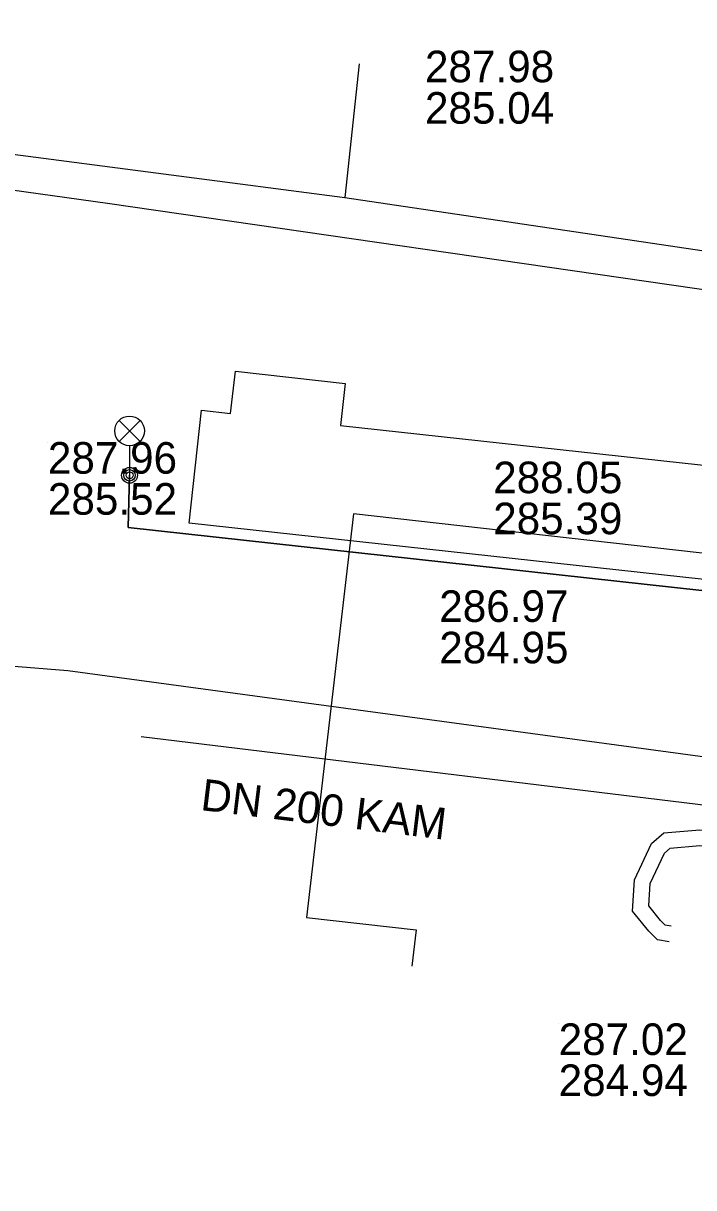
# Model space of a CAD drawing. Extents: x -595540 to -593988, y -1160850 to -1159202.
# Drawn here: x -594122.91 to -594105.92, y -1160212.47 to -1160182.95 of the extents above; entities that cross this region are included whole.
import ezdxf

# ---------------------------------------------------------------- set-up
doc = ezdxf.new("R2010")
doc.units = 0
for name, color, linetype in [('BVK-SPLASKOVA_popisy', 7, 'Continuous'), ('BVK-SPLASKOVA_trasa sítě', 7, 'Continuous'), ('DESTOVA-NEPROVOZOVANA_popisy', 7, 'Continuous'), ('DESTOVA_trasa neprovozované sítě', 7, 'Continuous'), ('EON-NN_kabel', 7, 'Continuous'), ('SPLASKOVA_neprovozovaná  trasa sítě', 7, 'Continuous'), ('SPLASKOVA_popisy neprovozované sítě', 7, 'Continuous'), ('TEPLARNY-TEPLOVODY_trasa sítě', 7, 'Continuous'), ('TSB_kabel VO', 7, 'Continuous'), ('TSB_kolektor', 7, 'Continuous'), ('TSB_lampy VO', 7, 'Continuous')]:
    doc.layers.add(name, color=color, linetype=linetype)

msp = doc.modelspace()

# ---------------------------------------------------------------- linework, layer by layer
at = {"layer": 'BVK-SPLASKOVA_popisy'}
for p, q in [((-594122.285, -1160193.567), (-594122.285, -1160193.567)), ((-594111.003, -1160194.062), (-594111.003, -1160194.062))]:
    msp.add_line(p, q, dxfattribs=at)
at = {"layer": 'BVK-SPLASKOVA_trasa sítě'}
for p, q in [((-594125.397, -1160186.863), (-594120.777, -1160187.51)), ((-594120.777, -1160187.51), (-594104.246, -1160189.903))]:
    msp.add_line(p, q, dxfattribs=at)
at = {"layer": 'DESTOVA-NEPROVOZOVANA_popisy'}
for p, q in [((-594112.731, -1160185.496), (-594112.731, -1160185.496)), ((-594112.369, -1160199.175), (-594112.369, -1160199.175))]:
    msp.add_line(p, q, dxfattribs=at)
at = {"layer": 'DESTOVA_trasa neprovozované sítě'}
for p, q in [((-594114.4, -1160183.982), (-594114.765, -1160187.369)), ((-594126.416, -1160185.847), (-594114.765, -1160187.369)), ((-594114.765, -1160187.369), (-594105.204, -1160188.788)), ((-594137.489, -1160198.059), (-594121.779, -1160199.36)), ((-594121.779, -1160199.36), (-594104.789, -1160201.659))]:
    msp.add_line(p, q, dxfattribs=at)
at = {"layer": 'EON-NN_kabel'}
for points in [[(-594106.543, -1160206.234), (-594106.84, -1160206.182), (-594107.062, -1160205.96), (-594107.47, -1160205.453), (-594107.421, -1160204.659), (-594106.991, -1160203.738), (-594106.684, -1160203.469), (-594105.765, -1160203.392), (-594104.788, -1160203.502), (-594101.807, -1160202.427), (-594101.138, -1160202.092), (-594099.842, -1160201.913), (-594098.971, -1160202.084), (-594097.92, -1160202.05), (-594097.689, -1160201.905), (-594096.842, -1160199.133), (-594096.818, -1160197.922)], [(-594106.493, -1160205.837), (-594106.646, -1160205.81), (-594106.764, -1160205.692), (-594107.062, -1160205.323), (-594107.027, -1160204.759), (-594106.665, -1160203.984), (-594106.52, -1160203.857), (-594105.771, -1160203.794), (-594104.74, -1160203.91), (-594101.649, -1160202.795), (-594101.018, -1160202.48), (-594099.854, -1160202.319), (-594099.003, -1160202.486), (-594097.798, -1160202.446), (-594097.351, -1160202.165), (-594096.443, -1160199.194), (-594096.419, -1160197.954)]]:
    msp.add_lwpolyline(points, dxfattribs=at)
at = {"layer": 'SPLASKOVA_neprovozovaná  trasa sítě'}
msp.add_line((-594119.925, -1160201.03), (-594101.338, -1160203.292), dxfattribs=at)
at = {"layer": 'SPLASKOVA_popisy neprovozované sítě'}
msp.add_line((-594109.344, -1160208.302), (-594109.344, -1160208.302), dxfattribs=at)
at = {"layer": 'TEPLARNY-TEPLOVODY_trasa sítě'}
msp.add_line((-594088.533, -1160198.325), (-594114.54, -1160195.386), dxfattribs=at)
msp.add_lwpolyline([(-594114.54, -1160195.386), (-594115.736, -1160205.616), (-594112.953, -1160205.931), (-594113.061, -1160206.847)], dxfattribs=at)
at = {"layer": 'TSB_kabel VO'}
msp.add_lwpolyline([(-594077.691, -1160180.065), (-594079.38, -1160198.67), (-594085.12, -1160199.607), (-594087.919, -1160199.331), (-594099.871, -1160197.975), (-594120.251, -1160195.733), (-594120.216, -1160194.409), (-594120.251, -1160195.733), (-594099.871, -1160197.975), (-594087.919, -1160199.331), (-594085.12, -1160199.607), (-594079.38, -1160198.67), (-594080.349, -1160200.766), (-594080.72, -1160203.896), (-594081.195, -1160204.233), (-594079.994, -1160204.418), (-594081.195, -1160204.233), (-594085.173, -1160204.005), (-594085.736, -1160207.087), (-594086.356, -1160212.085), (-594085.109, -1160213.084)], dxfattribs=at)
at = {"layer": 'TSB_kolektor'}
msp.add_lwpolyline([(-594090.376, -1160198.724), (-594118.707, -1160195.625), (-594118.394, -1160192.762), (-594117.655, -1160192.843), (-594117.534, -1160191.766), (-594114.751, -1160192.078), (-594114.871, -1160193.148), (-594090.063, -1160195.862)], close=True, dxfattribs=at)
at = {"layer": 'TSB_lampy VO'}
for p, q in [((-594120.481, -1160193.549), (-594119.951, -1160193.019)), ((-594120.481, -1160193.019), (-594119.951, -1160193.549)), ((-594120.481, -1160193.549), (-594119.951, -1160193.019)), ((-594120.481, -1160193.019), (-594119.951, -1160193.549)), ((-594120.216, -1160193.659), (-594120.216, -1160194.409)), ((-594120.216, -1160193.659), (-594120.216, -1160194.409))]:
    msp.add_line(p, q, dxfattribs=at)
for centre, radius in [((-594120.216, -1160193.284), 0.375), ((-594120.216, -1160193.284), 0.375), ((-594120.216, -1160194.409), 0.2), ((-594120.216, -1160194.409), 0.2), ((-594120.216, -1160194.409), 0.145), ((-594120.216, -1160194.409), 0.145), ((-594120.216, -1160194.409), 0.0876), ((-594120.216, -1160194.409), 0.0876)]:
    msp.add_circle(centre, radius, dxfattribs=at)

# ---------------------------------------------------------------- texts
at = {"layer": 'BVK-SPLASKOVA_popisy'}
for s, p in [('287.96', (-594122.285, -1160194.367)), ('288.05', (-594111.003, -1160194.862)), ('285.52', (-594122.285, -1160195.407)), ('285.39', (-594111.003, -1160195.902))]:
    msp.add_text(s, height=0.8, dxfattribs=at).set_placement(p)
at = {"layer": 'DESTOVA-NEPROVOZOVANA_popisy'}
for s, p in [('287.98', (-594112.731, -1160184.446)), ('285.04', (-594112.731, -1160185.496)), ('286.97', (-594112.369, -1160198.125)), ('284.95', (-594112.369, -1160199.175))]:
    msp.add_text(s, height=0.8, dxfattribs=at).set_placement(p)
at = {"layer": 'SPLASKOVA_popisy neprovozované sítě'}
msp.add_text('DN 200 KAM', height=0.8, rotation=353.0613, dxfattribs=at).set_placement((-594118.438, -1160202.892))
for s, p in [('287.02', (-594109.344, -1160209.102)), ('284.94', (-594109.344, -1160210.142))]:
    msp.add_text(s, height=0.8, dxfattribs=at).set_placement(p)

doc.saveas('drawing.dxf')
